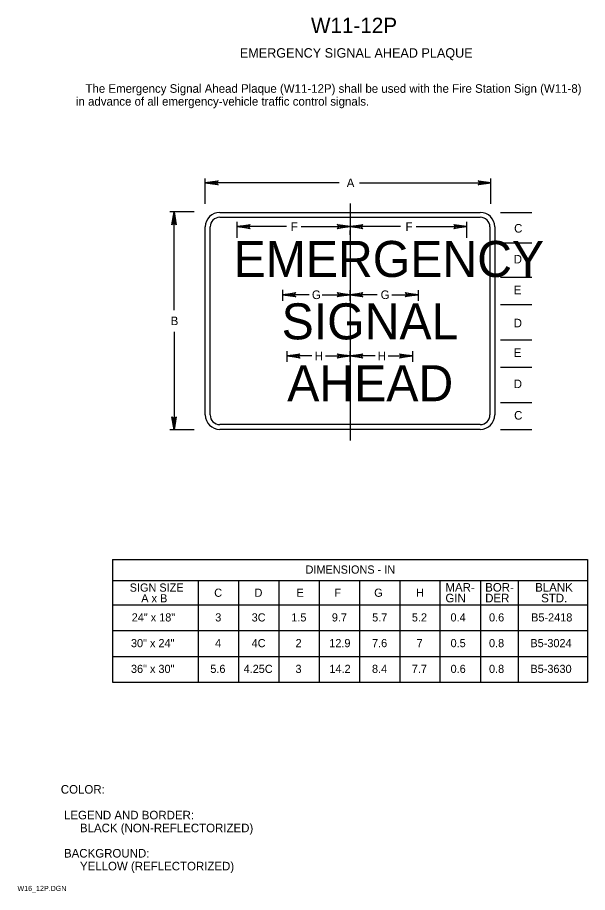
# Model space of a CAD drawing. Extents: x 0.013 to 0.179, y 0.004 to 0.259.
import ezdxf

# ---------------------------------------------------------------- set-up
doc = ezdxf.new("R2010")
doc.units = 0
for name, color, linetype in [('1', 7, 'Continuous'), ('2', 7, 'Continuous'), ('3', 7, 'Continuous')]:
    doc.layers.add(name, color=color, linetype=linetype)

# ---------------------------------------------------------------- blocks, each defined once
blk = doc.blocks.new('RARROW')
at = {"layer": '3'}
for p, q in [((-2.156, 0.285), (-2.2665, 0.384625)), ((-2.2665, 0.384625), (0, 0)), ((0, 0), (-2.2665, -0.379125)), ((-2.156, 0.285), (-2.075625, 0.12075)), ((0, 0), (-2.156, 0.285)), ((-2.14975, -0.2705), (0, 0)), ((-2.075625, 0.12075), (0, 0)), ((0, 0), (-2.074, -0.108)), ((-2.2665, -0.379125), (-2.14975, -0.2705)), ((-2.074, -0.108), (-2.14975, -0.2705))]:
    blk.add_line(p, q, dxfattribs=at)

msp = doc.modelspace()

# ---------------------------------------------------------------- linework, layer by layer
at = {"layer": '3'}
for p, q in [((0.06724, 0.20464), (0.06724, 0.21201)), ((0.15048, 0.20464), (0.15048, 0.21201)), ((0.10623, 0.21076), (0.06724, 0.21076)), ((0.11213, 0.21076), (0.15048, 0.21076)), ((0.10941, 0.20476), (0.10941, 0.13565)), ((0.06402, 0.20226), (0.05689, 0.20226)), ((0.05814, 0.17368), (0.05814, 0.20226)), ((0.07146, 0.20214), (0.14736, 0.20214)), ((0.15323, 0.20214), (0.16236, 0.20214)), ((0.07146, 0.20073), (0.14736, 0.20073)), ((0.07655, 0.19474), (0.07655, 0.19936)), ((0.14341, 0.19474), (0.14341, 0.19936)), ((0.06724, 0.14311), (0.06724, 0.19792)), ((0.06865, 0.14311), (0.06865, 0.19792)), ((0.09091, 0.19801), (0.07657, 0.19801)), ((0.09514, 0.19801), (0.10941, 0.19801)), ((0.12415, 0.19801), (0.10941, 0.19801)), ((0.10941, 0.19561), (0.10941, 0.19686)), ((0.12873, 0.19801), (0.14337, 0.19801)), ((0.15017, 0.19792), (0.15017, 0.14311)), ((0.15157, 0.19792), (0.15157, 0.14311)), ((0.15323, 0.19326), (0.16236, 0.19326)), ((0.15323, 0.18326), (0.16236, 0.18326)), ((0.08984, 0.17641), (0.08984, 0.17953)), ((0.10941, 0.17641), (0.10941, 0.17948)), ((0.12934, 0.17638), (0.12934, 0.17951)), ((0.09749, 0.17814), (0.08982, 0.17814)), ((0.10127, 0.17814), (0.10941, 0.17814)), ((0.11729, 0.17814), (0.10941, 0.17814)), ((0.12161, 0.17814), (0.12934, 0.17814)), ((0.15323, 0.17526), (0.16236, 0.17526)), ((0.05814, 0.16738), (0.05814, 0.13879)), ((0.15323, 0.16501), (0.16236, 0.16501)), ((0.0911, 0.15858), (0.0911, 0.16171)), ((0.10941, 0.15858), (0.10941, 0.16166)), ((0.12771, 0.15856), (0.12771, 0.16168)), ((0.09832, 0.16031), (0.09108, 0.16031)), ((0.10227, 0.16031), (0.10941, 0.16031)), ((0.11674, 0.16031), (0.10941, 0.16031)), ((0.12052, 0.16031), (0.12771, 0.16031)), ((0.15323, 0.15701), (0.16236, 0.15701)), ((0.15323, 0.14676), (0.16236, 0.14676)), ((0.14736, 0.14029), (0.07146, 0.14029)), ((0.06402, 0.13879), (0.05689, 0.13879)), ((0.14736, 0.13889), (0.07146, 0.13889)), ((0.15323, 0.13889), (0.16236, 0.13889)), ((0.0402, 0.101), (0.0402, 0.06525)), ((0.0402, 0.101), (0.17861, 0.101)), ((0.17861, 0.101), (0.17861, 0.06525)), ((0.0402, 0.09487), (0.17861, 0.09487)), ((0.06517, 0.09489), (0.06517, 0.06525)), ((0.0769, 0.09489), (0.0769, 0.06525)), ((0.08865, 0.09489), (0.08865, 0.06525)), ((0.1004, 0.09489), (0.1004, 0.06525)), ((0.11215, 0.09489), (0.11215, 0.06525)), ((0.12392, 0.09489), (0.12392, 0.06525)), ((0.13562, 0.09489), (0.13562, 0.06525)), ((0.14744, 0.09489), (0.14744, 0.06525)), ((0.1584, 0.09489), (0.1584, 0.06525)), ((0.0402, 0.08775), (0.17861, 0.08775)), ((0.0402, 0.08025), (0.17861, 0.08025)), ((0.0402, 0.07275), (0.17861, 0.07275)), ((0.0402, 0.06525), (0.17861, 0.06525))]:
    msp.add_line(p, q, dxfattribs=at)
for centre, radius, start, end in [((0.07146, 0.19792), 0.00422, 90, 180), ((0.14736, 0.19792), 0.00422, 0, 90), ((0.07146, 0.19792), 0.00281, 90, 180), ((0.14736, 0.19792), 0.00281, 0, 90), ((0.07146, 0.14311), 0.00422, 180, 270), ((0.07146, 0.14311), 0.00281, 180, 270), ((0.14736, 0.14311), 0.00422, 270, 0), ((0.14736, 0.14311), 0.00281, 270, 0)]:
    msp.add_arc(centre, radius, start, end, dxfattribs=at)

# ---------------------------------------------------------------- block references
at = {"layer": '3', "xscale": 0.0016545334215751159, "yscale": 0.0016366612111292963}
for p, rotation in [((0.06724, 0.21076), 180), ((0.05814, 0.20226), 90), ((0.07657, 0.19801), 180), ((0.10941, 0.19801), 180), ((0.08982, 0.17814), 180), ((0.10941, 0.17814), 180), ((0.09108, 0.16031), 180), ((0.10941, 0.16031), 180), ((0.05814, 0.13879), -90)]:
    msp.add_blockref('RARROW', p, dxfattribs=dict(at, rotation=rotation))
for p in [(0.15048, 0.21076), (0.10941, 0.19801), (0.14337, 0.19801), (0.10941, 0.17814), (0.12924, 0.17814), (0.10941, 0.16031), (0.1276, 0.16031)]:
    msp.add_blockref('RARROW', p, dxfattribs=at)

# ---------------------------------------------------------------- texts
at = {"layer": '1'}
for s, height, p in [('W11-12P', 0.0045, (0.09803, 0.25438)), ('EMERGENCY SIGNAL AHEAD PLAQUE', 0.0027503, (0.07729, 0.24725)), ('COLOR:', 0.0025, (0.02513, 0.03275)), (' LEGEND AND BORDER:', 0.0024998, (0.02513, 0.02525)), ('      BLACK (NON-REFLECTORIZED)', 0.0024998, (0.02513, 0.0215)), (' BACKGROUND:', 0.0024998, (0.02513, 0.01413)), ('      YELLOW (REFLECTORIZED)', 0.0024998, (0.02513, 0.01038)), ('W16_12P.DGN', 0.0015, (0.0125, 0.00438))]:
    msp.add_text(s, height=height, dxfattribs=at).set_placement(p)
at = {"layer": '2'}
for s, p in [('   The Emergency Signal Ahead Plaque (W11-12P) shall be used with the Fire Station Sign (W11-8) ', (0.02953, 0.237)), ('in advance of all emergency-vehicle traffic control signals.', (0.02953, 0.23325))]:
    msp.add_text(s, height=0.0024998, dxfattribs=at).set_placement(p)
at = {"layer": '3'}
for s, height, p in [('A', 0.0025, (0.10845, 0.20951)), ('F', 0.0025, (0.09215, 0.19676)), ('F', 0.0025, (0.12558, 0.19676)), ('C', 0.0025, (0.15723, 0.19626)), ('EMERGENCY', 0.0105, (0.07547, 0.18332)), ('D', 0.0025, (0.15711, 0.18726)), ('G', 0.0025, (0.0983, 0.17689)), ('G', 0.0025, (0.11834, 0.17689)), ('E', 0.0025, (0.15711, 0.17826)), ('SIGNAL', 0.0105, (0.08948, 0.16514)), ('B', 0.0025, (0.05714, 0.16928)), ('D', 0.0025, (0.15711, 0.16864)), ('H', 0.0025, (0.09911, 0.15906)), ('H', 0.0025, (0.11746, 0.15906)), ('E', 0.0025, (0.15711, 0.16001)), ('AHEAD', 0.0105, (0.09111, 0.14711)), ('D', 0.0025, (0.15711, 0.15092)), ('C', 0.0025, (0.15723, 0.14176)), ('DIMENSIONS - IN', 0.0023752, (0.09645, 0.09687)), ('SIGN SIZE', 0.002375, (0.0452, 0.09162)), ('C', 0.00238, (0.06983, 0.09012)), ('D', 0.00238, (0.08158, 0.09012)), ('E', 0.00238, (0.09383, 0.09012)), ('F', 0.00238, (0.10483, 0.09012)), ('G', 0.00238, (0.11645, 0.09012)), ('H', 0.00238, (0.12868, 0.09012)), ('MAR-', 0.0025, (0.13721, 0.09162)), ('BOR-', 0.0025, (0.1488, 0.09162)), ('BLANK', 0.0025, (0.16336, 0.09162)), ('A x B', 0.002375, (0.04858, 0.0885)), ('GIN', 0.0025, (0.13721, 0.0885)), ('DER', 0.0025, (0.1488, 0.0885)), ('STD.', 0.0025, (0.16511, 0.0885)), ('24" x 18"', 0.002375, (0.04579, 0.08293)), ('3', 0.00238, (0.07013, 0.08293)), ('3C', 0.002375, (0.08074, 0.08293)), ('1.5', 0.002375, (0.09229, 0.08293)), ('9.7', 0.002375, (0.10411, 0.08293)), ('5.7', 0.002375, (0.11586, 0.08293)), ('5.2', 0.002375, (0.12743, 0.08293)), ('0.4', 0.002375, (0.13869, 0.08293)), ('0.6', 0.002375, (0.14992, 0.08293)), ('B5-2418', 0.002375, (0.16219, 0.08293)), ('30" x 24"', 0.002375, (0.04557, 0.07543)), ('4', 0.00238, (0.07009, 0.07543)), ('4C', 0.002375, (0.08074, 0.07543)), ('2', 0.00238, (0.09353, 0.07543)), ('12.9', 0.002375, (0.10336, 0.07543)), ('7.6', 0.002375, (0.11582, 0.07543)), ('7', 0.00238, (0.12881, 0.07543)), ('0.5', 0.002375, (0.13871, 0.07543)), ('0.8', 0.002375, (0.14991, 0.07543)), ('B5-3024', 0.002375, (0.16197, 0.07543)), ('36" x 30"', 0.002375, (0.04557, 0.06793)), ('5.6', 0.002375, (0.0687, 0.06793)), ('4.25C', 0.002375, (0.0784, 0.06793)), ('3', 0.00238, (0.09351, 0.06793)), ('14.2', 0.002375, (0.1034, 0.06793)), ('8.4', 0.002375, (0.11581, 0.06793)), ('7.7', 0.002375, (0.12741, 0.06793)), ('0.6', 0.002375, (0.13871, 0.06793)), ('0.8', 0.002375, (0.14991, 0.06793)), ('B5-3630', 0.002375, (0.16198, 0.06793))]:
    msp.add_text(s, height=height, dxfattribs=at).set_placement(p)

doc.saveas('drawing.dxf')
